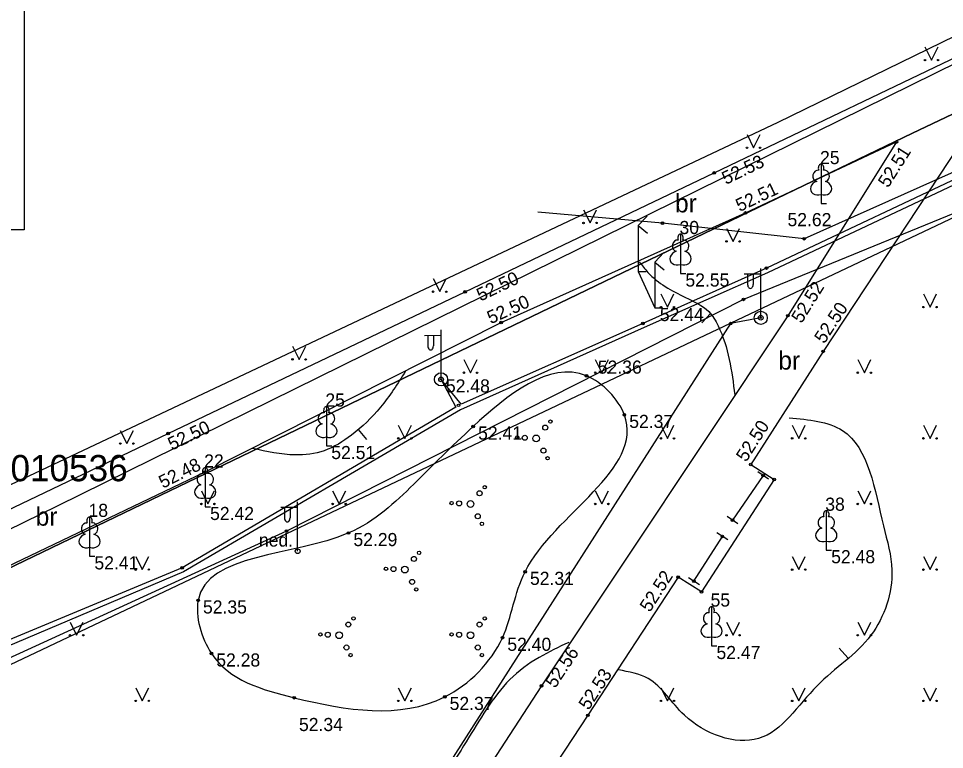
# Model space of a CAD drawing. Extents: x 619806 to 620082, y 405176 to 405386.
# Drawn here: x 619897.79 to 619933.05, y 405325.65 to 405353.49 of the extents above; entities that cross this region are included whole.
import ezdxf

# ---------------------------------------------------------------- set-up
doc = ezdxf.new("R2010")
doc.units = 0
for name, color, linetype in [('24', 7, 'Continuous'), ('APGR_SARK_####_####_#', 7, 'Continuous'), ('APGS_ELEM_####_####_#', 7, 'Continuous'), ('APGS_ELEM_####_TKST_#', 7, 'Continuous'), ('APGS_VADP_ZSPR_####_#', 7, 'Continuous'), ('BUVE_SOLS_####_####_#', 7, 'Continuous'), ('CELI_CMAL_####_####_#', 7, 'Continuous'), ('CELI_CSEG_####_TKST_#', 7, 'Continuous'), ('CELI_ELEM_####_####_#', 7, 'Continuous'), ('CELI_REKL_####_####_#', 7, 'Continuous'), ('ELEK_VADP_ZSPR_####_#', 7, 'Continuous'), ('RAMI_PLAN_####_TKST_#', 7, 'Continuous'), ('RAMI_UZMR_####_####_#', 7, 'Continuous'), ('RELJ_AATZ_####_TKST_#', 7, 'Continuous'), ('RELJ_ELEM_####_####_#', 7, 'Continuous'), ('RELJ_HORZ_PAMT_####_#', 7, 'Continuous'), ('ROBZ_PROJ_####_TKST_#', 7, 'Continuous'), ('ROBZ_UZMR_####_####_#', 7, 'Continuous'), ('SAKT_VADP_KABE_####_#', 7, 'Continuous'), ('TERT_DIAM_####_TKST_#', 7, 'Continuous'), ('TERT_ELEM_####_####_#', 7, 'Continuous'), ('TERT_KONT_####_####_#', 7, 'Continuous')]:
    doc.layers.add(name, color=color, linetype=linetype)

msp = doc.modelspace()

# ---------------------------------------------------------------- linework, layer by layer
at = {"layer": '24'}
for p, q in [((619934.749, 405350.522), (619931.837, 405349.12)), ((619931.837, 405349.12), (619818.193, 405294.391))]:
    msp.add_line(p, q, dxfattribs=at)
at = {"layer": 'APGR_SARK_####_####_#'}
msp.add_lwpolyline([(619818.56, 405291.467), (619964.609, 405360.731), (619976.198, 405343.424)], dxfattribs=at)
at = {"layer": 'APGS_ELEM_####_####_#'}
for p, q in [((619926.053, 405342.093), (619926.053, 405343.976)), ((619926.053, 405343.76), (619925.418, 405343.755)), ((619925.553, 405343.756), (619925.553, 405343.364)), ((619925.763, 405343.758), (619925.763, 405343.364)), ((619913.878, 405341.415), (619913.243, 405341.41)), ((619913.378, 405341.411), (619913.378, 405341.019)), ((619913.588, 405341.413), (619913.588, 405341.019)), ((619913.878, 405339.748), (619913.878, 405341.631)), ((619908.418, 405333.2), (619908.418, 405335.083)), ((619908.418, 405334.867), (619907.783, 405334.862)), ((619907.918, 405334.863), (619907.918, 405334.471)), ((619908.128, 405334.865), (619908.128, 405334.471))]:
    msp.add_line(p, q, dxfattribs=at)
for centre, radius in [((619926.053, 405342.093), 0.25), ((619926.053, 405342.093), 0.09), ((619926.053, 405342.093), 0.0225), ((619913.878, 405339.748), 0.25), ((619913.878, 405339.748), 0.09), ((619913.878, 405339.748), 0.0225), ((619908.418, 405333.2), 0.09)]:
    msp.add_circle(centre, radius, dxfattribs=at)
for centre in [(619925.658, 405343.364), (619913.483, 405341.019), (619908.023, 405334.471)]:
    msp.add_ellipse(centre, major_axis=(0, 0.151), ratio=0.695971, start_param=1.570796, end_param=4.712389, dxfattribs=at)
at = {"layer": 'APGS_VADP_ZSPR_####_#'}
for points in [[(619961.504, 405361.726), (619961.549, 405360.889), (619955.561, 405357.47), (619948.629, 405353.911), (619942.586, 405351.309), (619934.737, 405347.784), (619926.308, 405343.807), (619921.62, 405341.722), (619914.616, 405338.589), (619904.064, 405332.419), (619892.947, 405327.707), (619882.253, 405322.432), (619872.343, 405318.394), (619866.043, 405315.914), (619858.147, 405313.031), (619849.141, 405308.474), (619837.591, 405302.476), (619829.867, 405298.738), (619827.533, 405297.619), (619826.332, 405294.789), (619825.868, 405290.973), (619826.009, 405290.873), (619827.279, 405290.766)], [(619961.504, 405361.726), (619961.582, 405360.944), (619961.547, 405359.255), (619942.312, 405349.715), (619925.4, 405342.794), (619907.997, 405333.971), (619887.51, 405324.581), (619867.415, 405316.417), (619859.827, 405308.06), (619845.28, 405301.51), (619837.164, 405301.798), (619827.1, 405298.963), (619826.475, 405294.709), (619826.025, 405290.988), (619827.279, 405290.766)], [(619961.504, 405361.726), (619961.513, 405360.941), (619956.997, 405358.363), (619948.588, 405354.007), (619942.536, 405351.427), (619934.667, 405347.943), (619926.276, 405343.988), (619921.568, 405341.876), (619914.639, 405338.805), (619913.878, 405339.748), (619914.447, 405338.686), (619904.019, 405332.565), (619892.911, 405327.951)], [(619926.053, 405342.093), (619924.906, 405341.871), (619913.437, 405323.942), (619914.167, 405323.421), (619913.311, 405323.727), (619901.199, 405304.503), (619901.88, 405304.137), (619901.118, 405304.337), (619891.212, 405294.458), (619889.151, 405287.633)]]:
    msp.add_lwpolyline(points, dxfattribs=at)
at = {"layer": 'BUVE_SOLS_####_####_#'}
for p, q in [((619926.149, 405336.083), (619924.978, 405334.383)), ((619926.355, 405335.941), (619925.943, 405336.225)), ((619925.184, 405334.241), (619924.772, 405334.525)), ((619923.51, 405332.059), (619924.591, 405333.767)), ((619924.802, 405333.633), (619924.38, 405333.901)), ((619923.721, 405331.925), (619923.299, 405332.193))]:
    msp.add_line(p, q, dxfattribs=at)
at = {"layer": 'CELI_CMAL_####_####_#'}
for points in [[(619991.854, 405321.355), (619987.265, 405327.894), (619980.195, 405338.024), (619973.089, 405348.264), (619967.033, 405357.029), (619962.383, 405363.658), (619953.25, 405359.322), (619947.967, 405356.794), (619934.832, 405350.507), (619928.431, 405340.813), (619925.67, 405336.505), (619926.565, 405335.935), (619923.8, 405331.651)], [(619825.042, 405301.626), (619825.997, 405300.736), (619826.865, 405300.888), (619837.411, 405305.982), (619845.924, 405310.094), (619856.691, 405315.252), (619868.203, 405320.761), (619880.848, 405326.828), (619891.162, 405331.79), (619903.487, 405337.685), (619914.792, 405343.079), (619924.282, 405347.611), (619934.782, 405352.643), (619943.391, 405356.735), (619942.998, 405357.499)], [(619889.516, 405328.858), (619904.867, 405336.211), (619916.17, 405341.916), (619925.47, 405346.087), (619931.221, 405348.79)], [(619931.221, 405348.79), (619927.084, 405342.173), (619917.705, 405328.076), (619912.167, 405319.566), (619908.262, 405313.163), (619901.141, 405301.297), (619895.285, 405291.495)], [(619923.8, 405331.651), (619922.909, 405332.209), (619919.472, 405326.95), (619913.839, 405318.4), (619910.247, 405312.462), (619903.419, 405300.947), (619897.856, 405291.596), (619907.48, 405291.973), (619918.115, 405292.304), (619928.883, 405292.628), (619940.313, 405293.006), (619951.468, 405293.381)]]:
    msp.add_lwpolyline(points, dxfattribs=at)
at = {"layer": 'CELI_ELEM_####_####_#'}
for points in [[(619921.728, 405345.969), (619921.386, 405345.613), (619921.742, 405345.314)], [(619921.386, 405345.613), (619921.386, 405343.861), (619921.685, 405343.861)], [(619922.367, 405344.574), (619922.025, 405344.218), (619922.381, 405343.919)], [(619922.025, 405344.218), (619922.025, 405342.466), (619922.324, 405342.466)]]:
    msp.add_lwpolyline(points, dxfattribs=at)
at = {"layer": 'CELI_REKL_####_####_#'}
msp.add_lwpolyline([(619921.386, 405343.861), (619922.025, 405342.466)], dxfattribs=at)
at = {"layer": 'ELEK_VADP_ZSPR_####_#'}
msp.add_lwpolyline([(619971.958, 405366.357), (619953.365, 405356.579), (619942.947, 405351.901), (619927.707, 405345.105), (619922.312, 405345.694), (619917.565, 405346.118)], dxfattribs=at)
at = {"layer": 'RAMI_PLAN_####_TKST_#'}
msp.add_lwpolyline([(619883.741, 405345.448), (619883.741, 405364.759), (619898.001, 405364.759), (619898.001, 405345.448)], close=True, dxfattribs=at)
at = {"layer": 'RAMI_UZMR_####_####_#'}
msp.add_lwpolyline([(619874.687, 405324.979), (619926.719, 405349.544), (619966.669, 405369.042), (620021.738, 405292.03), (620049.703, 405275.476), (620026.189, 405242.287), (620012.147, 405222.917), (619996.603, 405200.928), (619989.997, 405199.173), (619982.328, 405199.155), (619922.669, 405233.014), (619882.137, 405255.756), (619859.084, 405268.056), (619820.646, 405290.715), (619813.744, 405295.206), (619820.645, 405298.752)], close=True, dxfattribs=at)
at = {"layer": 'RELJ_ELEM_####_####_#'}
for centre in [(619931.221, 405348.79), (619924.282, 405347.611), (619925.47, 405346.087), (619922.312, 405345.694), (619927.707, 405345.105), (619926.276, 405343.988), (619914.792, 405343.079), (619925.4, 405342.794), (619927.084, 405342.173), (619916.17, 405341.916), (619921.568, 405341.876), (619924.906, 405341.871), (619928.431, 405340.813), (619919.417, 405339.883), (619914.544, 405338.758), (619920.859, 405338.396), (619915.104, 405337.953), (619903.487, 405337.685), (619925.67, 405336.505), (619904.867, 405336.211), (619926.149, 405336.083), (619926.565, 405335.935), (619924.978, 405334.383), (619907.997, 405333.971), (619910.356, 405333.895), (619924.591, 405333.767), (619904.019, 405332.565), (619917.079, 405332.417), (619922.909, 405332.209), (619923.51, 405332.059), (619923.8, 405331.651), (619904.626, 405331.328), (619916.216, 405329.906), (619905.132, 405329.307), (619917.705, 405328.076), (619908.283, 405327.62), (619914.02, 405327.653), (619919.472, 405326.95)]:
    msp.add_circle(centre, 0.05, dxfattribs=at)
at = {"layer": 'RELJ_HORZ_PAMT_####_#'}
for p, q in [((619923.816, 405341.896), (619924.155, 405342.264)), ((619911.056, 405337.455), (619910.741, 405337.843)), ((619929.037, 405329.505), (619929.376, 405329.137))]:
    msp.add_line(p, q, dxfattribs=at)
for points in [[(619921.426, 405344.224), (619921.758, 405343.821), (619923.187, 405342.867), (619924.073, 405342.329), (619924.429, 405341.789), (619925.066, 405339.155)], [(619912.527, 405340.062), (619911.571, 405338.683), (619910.462, 405337.62), (619909.43, 405337.031), (619908.327, 405336.869), (619906.693, 405337.117)], [(619927.135, 405338.286), (619929.164, 405337.801), (619930.728, 405334.167), (619931.051, 405332.479), (619930.25, 405330), (619928.199, 405328.075), (619925.971, 405326.066), (619923.148, 405326.954), (619921.766, 405328.348), (619920.633, 405328.681)], [(619918.742, 405329.729), (619917.612, 405329.154), (619916.499, 405328.312), (619915.614, 405327.187), (619914.833, 405325.938), (619914.442, 405325.317), (619914.031, 405324.725), (619913.331, 405323.789), (619912.64, 405322.847), (619911.31, 405320.969), (619910.015, 405319.069), (619908.767, 405317.139), (619908.164, 405316.159), (619907.577, 405315.169), (619906.955, 405314.022), (619906.379, 405312.85), (619905.821, 405311.67), (619905.539, 405311.083), (619905.25, 405310.5), (619905.107, 405310.256), (619904.948, 405310.016), (619904.743, 405309.66), (619904.718, 405309.601), (619904.698, 405309.542), (619904.72, 405309.402), (619904.84, 405309.271), (619905.01, 405309.174), (619905.183, 405309.136), (619905.828, 405309.136)]]:
    msp.add_spline(points, degree=3, dxfattribs=at)
at = {"layer": 'ROBZ_UZMR_####_####_#'}
for p, q in [((619931.837, 405349.12), (619934.749, 405350.522)), ((619818.193, 405294.391), (619931.837, 405349.12))]:
    msp.add_line(p, q, dxfattribs=at)
at = {"layer": 'SAKT_VADP_KABE_####_#'}
msp.add_lwpolyline([(619816.151, 405294.73), (619838.42, 405305.23), (619866.149, 405318.697), (619899.278, 405334.929), (619937.202, 405353.635), (619962.924, 405366.289), (619964.424, 405369.208)], dxfattribs=at)
at = {"layer": 'TERT_ELEM_####_####_#'}
for p, q in [((619932.308, 405352.41), (619932.558, 405351.91)), ((619932.558, 405351.91), (619932.808, 405352.41)), ((619925.531, 405349.07), (619925.781, 405348.57)), ((619925.781, 405348.57), (619926.031, 405349.07)), ((619928.352, 405346.793), (619928.352, 405346.446)), ((619928.352, 405346.446), (619928.552, 405346.446)), ((619919.304, 405346.206), (619919.554, 405345.706)), ((619919.554, 405345.706), (619919.804, 405346.206)), ((619924.75, 405345.5), (619925, 405345)), ((619925, 405345), (619925.25, 405345.5)), ((619922.999, 405344.129), (619922.999, 405343.782)), ((619913.577, 405343.588), (619913.827, 405343.088)), ((619913.827, 405343.088), (619914.077, 405343.588)), ((619922.999, 405343.782), (619923.199, 405343.782)), ((619922.25, 405343), (619922.5, 405342.5)), ((619922.5, 405342.5), (619922.75, 405343)), ((619932.25, 405343), (619932.5, 405342.5)), ((619932.5, 405342.5), (619932.75, 405343)), ((619908.223, 405341.008), (619908.473, 405340.508)), ((619908.473, 405340.508), (619908.723, 405341.008)), ((619914.75, 405340.5), (619915, 405340)), ((619915, 405340), (619915.25, 405340.5)), ((619919.75, 405340.5), (619920, 405340)), ((619920, 405340), (619920.25, 405340.5)), ((619929.75, 405340.5), (619930, 405340)), ((619930, 405340), (619930.25, 405340.5)), ((619912.25, 405338), (619912.5, 405337.5)), ((619912.5, 405337.5), (619912.75, 405338)), ((619922.25, 405338), (619922.5, 405337.5)), ((619922.5, 405337.5), (619922.75, 405338)), ((619927.25, 405338), (619927.5, 405337.5)), ((619927.5, 405337.5), (619927.75, 405338)), ((619932.25, 405338), (619932.5, 405337.5)), ((619932.5, 405337.5), (619932.75, 405338)), ((619901.664, 405337.802), (619901.914, 405337.302)), ((619901.914, 405337.302), (619902.164, 405337.802)), ((619909.513, 405337.557), (619909.513, 405337.21)), ((619909.513, 405337.21), (619909.713, 405337.21)), ((619904.75, 405335.5), (619905, 405335)), ((619905, 405335), (619905.25, 405335.5)), ((619909.75, 405335.5), (619910, 405335)), ((619910, 405335), (619910.25, 405335.5)), ((619919.75, 405335.5), (619920, 405335)), ((619920, 405335), (619920.25, 405335.5)), ((619929.75, 405335.5), (619930, 405335)), ((619930, 405335), (619930.25, 405335.5)), ((619904.897, 405335.236), (619904.897, 405334.889)), ((619904.897, 405334.889), (619905.097, 405334.889)), ((619900.492, 405333.355), (619900.492, 405333.008)), ((619928.55, 405333.589), (619928.55, 405333.242)), ((619900.492, 405333.008), (619900.692, 405333.008)), ((619902.25, 405333), (619902.5, 405332.5)), ((619902.5, 405332.5), (619902.75, 405333)), ((619927.25, 405333), (619927.5, 405332.5)), ((619927.5, 405332.5), (619927.75, 405333)), ((619928.55, 405333.242), (619928.75, 405333.242)), ((619932.25, 405333), (619932.5, 405332.5)), ((619932.5, 405332.5), (619932.75, 405333)), ((619899.75, 405330.5), (619900, 405330)), ((619900, 405330), (619900.25, 405330.5)), ((619924.75, 405330.5), (619925, 405330)), ((619925, 405330), (619925.25, 405330.5)), ((619929.75, 405330.5), (619930, 405330)), ((619930, 405330), (619930.25, 405330.5)), ((619924.182, 405329.94), (619924.182, 405329.593)), ((619924.182, 405329.593), (619924.382, 405329.593)), ((619902.25, 405328), (619902.5, 405327.5)), ((619902.5, 405327.5), (619902.75, 405328)), ((619912.25, 405328), (619912.5, 405327.5)), ((619912.5, 405327.5), (619912.75, 405328)), ((619922.25, 405328), (619922.5, 405327.5)), ((619922.5, 405327.5), (619922.75, 405328)), ((619927.25, 405328), (619927.5, 405327.5)), ((619927.5, 405327.5), (619927.75, 405328)), ((619932.25, 405328), (619932.5, 405327.5)), ((619932.5, 405327.5), (619932.75, 405328))]:
    msp.add_line(p, q, dxfattribs=at)
for points in [[(619928.352, 405347.946), (619928.352, 405346.793)], [(619928.442, 405347.714), (619928.441, 405347.715)], [(619922.999, 405345.282), (619922.999, 405344.129)], [(619923.089, 405345.05), (619923.088, 405345.051)], [(619909.513, 405338.71), (619909.513, 405337.557)], [(619909.603, 405338.478), (619909.602, 405338.479)], [(619904.897, 405336.389), (619904.897, 405335.236)], [(619904.987, 405336.157), (619904.986, 405336.158)], [(619928.55, 405334.742), (619928.55, 405333.589)], [(619900.492, 405334.508), (619900.492, 405333.355)], [(619928.64, 405334.51), (619928.639, 405334.511)], [(619900.582, 405334.276), (619900.581, 405334.277)], [(619924.182, 405331.093), (619924.182, 405329.94)], [(619924.272, 405330.861), (619924.271, 405330.862)]]:
    msp.add_lwpolyline(points, dxfattribs=at)
for centre, radius in [((619932.308, 405351.91), 0.028), ((619932.808, 405351.91), 0.0263), ((619925.531, 405348.569), 0.028), ((619926.031, 405348.569), 0.0263), ((619919.304, 405345.706), 0.028), ((619919.804, 405345.706), 0.0263), ((619924.75, 405345), 0.028), ((619925.25, 405345), 0.0263), ((619913.577, 405343.087), 0.028), ((619914.077, 405343.087), 0.0263), ((619922.25, 405342.5), 0.028), ((619922.75, 405342.5), 0.0263), ((619932.25, 405342.5), 0.028), ((619932.75, 405342.5), 0.0263), ((619908.222, 405340.508), 0.028), ((619908.722, 405340.508), 0.0263), ((619914.75, 405340), 0.028), ((619915.25, 405340), 0.0263), ((619919.75, 405340), 0.028), ((619920.25, 405340), 0.0263), ((619929.75, 405340), 0.028), ((619930.25, 405340), 0.0263), ((619918.044, 405338.139), 0.064), ((619917.848, 405337.908), 0.096), ((619912.25, 405337.5), 0.028), ((619912.75, 405337.5), 0.0263), ((619916.782, 405337.534), 0.064), ((619917.066, 405337.521), 0.096), ((619917.5, 405337.5), 0.128), ((619922.25, 405337.5), 0.028), ((619922.75, 405337.5), 0.0263), ((619927.25, 405337.5), 0.028), ((619927.75, 405337.5), 0.0263), ((619932.25, 405337.5), 0.028), ((619932.75, 405337.5), 0.0263), ((619901.663, 405337.301), 0.028), ((619902.163, 405337.301), 0.0263), ((619917.776, 405337.033), 0.096), ((619917.934, 405336.744), 0.064), ((619915.348, 405335.408), 0.096), ((619915.544, 405335.639), 0.064), ((619904.75, 405335), 0.028), ((619905.25, 405335), 0.0263), ((619909.75, 405335), 0.028), ((619910.25, 405335), 0.0263), ((619914.282, 405335.034), 0.064), ((619914.566, 405335.021), 0.096), ((619915, 405335), 0.128), ((619919.75, 405335), 0.028), ((619920.25, 405335), 0.0263), ((619929.75, 405335), 0.028), ((619930.25, 405335), 0.0263), ((619915.276, 405334.533), 0.096), ((619915.434, 405334.244), 0.064), ((619912.848, 405332.908), 0.096), ((619913.044, 405333.139), 0.064), ((619911.782, 405332.534), 0.064), ((619912.066, 405332.521), 0.096), ((619912.5, 405332.5), 0.128), ((619902.25, 405332.5), 0.028), ((619902.75, 405332.5), 0.0263), ((619927.25, 405332.5), 0.028), ((619927.75, 405332.5), 0.0263), ((619932.25, 405332.5), 0.028), ((619932.75, 405332.5), 0.0263), ((619912.776, 405332.033), 0.096), ((619912.934, 405331.744), 0.064), ((619910.348, 405330.408), 0.096), ((619910.544, 405330.639), 0.064), ((619915.348, 405330.408), 0.096), ((619915.544, 405330.639), 0.064), ((619909.282, 405330.034), 0.064), ((619909.566, 405330.021), 0.096), ((619910, 405330), 0.128), ((619914.282, 405330.034), 0.064), ((619914.566, 405330.021), 0.096), ((619915, 405330), 0.128), ((619899.75, 405330), 0.028), ((619900.25, 405330), 0.0263), ((619924.75, 405330), 0.028), ((619925.25, 405330), 0.0263), ((619929.75, 405330), 0.028), ((619930.25, 405330), 0.0263), ((619910.276, 405329.533), 0.096), ((619915.276, 405329.533), 0.096), ((619910.434, 405329.244), 0.064), ((619915.434, 405329.244), 0.064), ((619902.25, 405327.5), 0.028), ((619902.75, 405327.5), 0.0263), ((619912.25, 405327.5), 0.028), ((619912.75, 405327.5), 0.0263), ((619922.25, 405327.5), 0.028), ((619922.75, 405327.5), 0.0263), ((619927.25, 405327.5), 0.028), ((619927.75, 405327.5), 0.0263), ((619932.25, 405327.5), 0.028), ((619932.75, 405327.5), 0.0263)]:
    msp.add_circle(centre, radius, dxfattribs=at)
for centre, major_axis, ratio, start_param, end_param in [((619928.224, 405347.501), (-0.039, -0.212), 0.861323, 3.141593, 6.283185), ((619928.352, 405347.796), (0, -0.15), 0.707107, 3.14537, 5.287485), ((619928.352, 405347.796), (0, -0.15), 0.707107, 0.995701, 3.137816), ((619928.48, 405347.501), (0.039, -0.212), 0.861323, 0, 3.141593), ((619928.262, 405347.039), (0.307, 0.095), 0.814445, 1.570796, 4.752015), ((619928.442, 405347.039), (-0.307, 0.095), 0.814445, 1.531171, 4.712389), ((619922.999, 405345.132), (0, -0.15), 0.707107, 3.14537, 5.287485), ((619922.999, 405345.132), (0, -0.15), 0.707107, 0.995701, 3.137816), ((619922.871, 405344.837), (-0.039, -0.212), 0.861323, 3.141593, 6.283185), ((619923.127, 405344.837), (0.039, -0.212), 0.861323, 0, 3.141593), ((619922.909, 405344.375), (0.307, 0.095), 0.814445, 1.570796, 4.752015), ((619923.089, 405344.375), (-0.307, 0.095), 0.814445, 1.531171, 4.712389), ((619909.513, 405338.56), (0, -0.15), 0.707107, 3.14537, 5.287485), ((619909.513, 405338.56), (0, -0.15), 0.707107, 0.995701, 3.137816), ((619909.385, 405338.265), (-0.039, -0.212), 0.861323, 3.141593, 6.283185), ((619909.641, 405338.265), (0.039, -0.212), 0.861323, 0, 3.141593), ((619909.423, 405337.803), (0.307, 0.095), 0.814445, 1.570796, 4.752015), ((619909.603, 405337.803), (-0.307, 0.095), 0.814445, 1.531171, 4.712389), ((619904.769, 405335.944), (-0.039, -0.212), 0.861323, 3.141593, 6.283185), ((619904.897, 405336.239), (0, -0.15), 0.707107, 3.14537, 5.287485), ((619904.897, 405336.239), (0, -0.15), 0.707107, 0.995701, 3.137816), ((619905.025, 405335.944), (0.039, -0.212), 0.861323, 0, 3.141593), ((619904.807, 405335.482), (0.307, 0.095), 0.814445, 1.570796, 4.752015), ((619904.987, 405335.482), (-0.307, 0.095), 0.814445, 1.531171, 4.712389), ((619928.55, 405334.592), (0, -0.15), 0.707107, 3.14537, 5.287485), ((619928.55, 405334.592), (0, -0.15), 0.707107, 0.995701, 3.137816), ((619900.492, 405334.358), (0, -0.15), 0.707107, 3.14537, 5.287485), ((619900.492, 405334.358), (0, -0.15), 0.707107, 0.995701, 3.137816), ((619928.422, 405334.297), (-0.039, -0.212), 0.861323, 3.141593, 6.283185), ((619928.678, 405334.297), (0.039, -0.212), 0.861323, 0, 3.141593), ((619900.364, 405334.063), (-0.039, -0.212), 0.861323, 3.141593, 6.283185), ((619900.62, 405334.063), (0.039, -0.212), 0.861323, 0, 3.141593), ((619928.46, 405333.835), (0.307, 0.095), 0.814445, 1.570796, 4.752015), ((619928.64, 405333.835), (-0.307, 0.095), 0.814445, 1.531171, 4.712389), ((619900.402, 405333.601), (0.307, 0.095), 0.814445, 1.570796, 4.752015), ((619900.582, 405333.601), (-0.307, 0.095), 0.814445, 1.531171, 4.712389), ((619924.054, 405330.648), (-0.039, -0.212), 0.861323, 3.141593, 6.283185), ((619924.182, 405330.943), (0, -0.15), 0.707107, 3.14537, 5.287485), ((619924.182, 405330.943), (0, -0.15), 0.707107, 0.995701, 3.137816), ((619924.31, 405330.648), (0.039, -0.212), 0.861323, 0, 3.141593), ((619924.092, 405330.186), (0.307, 0.095), 0.814445, 1.570796, 4.752015), ((619924.272, 405330.186), (-0.307, 0.095), 0.814445, 1.531171, 4.712389)]:
    msp.add_ellipse(centre, major_axis=major_axis, ratio=ratio, start_param=start_param, end_param=end_param, dxfattribs=at)
at = {"layer": 'TERT_KONT_####_####_#'}
msp.add_spline([(619912.845, 405335.757), (619915.104, 405337.953), (619919.417, 405339.883), (619920.859, 405338.396), (619917.079, 405332.417), (619916.216, 405329.906), (619914.02, 405327.653), (619908.283, 405327.62), (619905.132, 405329.307), (619904.626, 405331.328), (619910.356, 405333.895), (619912.845, 405335.757)], degree=3, dxfattribs=at)

# ---------------------------------------------------------------- texts
at = {"layer": 'APGS_ELEM_####_TKST_#'}
msp.add_text('ned.', height=0.5, dxfattribs=at).set_placement((619906.943, 405333.376))
at = {"layer": 'CELI_CSEG_####_TKST_#'}
for p in [(619922.788, 405346.108), (619926.724, 405340.118), (619898.44, 405334.173)]:
    msp.add_text('br', height=0.7, dxfattribs=at).set_placement(p)
at = {"layer": 'RELJ_AATZ_####_TKST_#'}
for s, rotation, p in [(' 52.51', 57.6698, (619930.806, 405346.858)), (' 52.53', 25.6055, (619924.557, 405347.072)), (' 52.51', 25.1738, (619925.08, 405346.04)), (' 52.50', 25.5271, (619915.214, 405342.628)), (' 52.52', 57.9861, (619927.508, 405341.694)), (' 52.50', 24.156, (619915.602, 405341.769)), (' 52.50', 56.563, (619928.37, 405340.921)), (' 52.50', 25.5074, (619903.458, 405336.95)), (' 52.50', 57.3442, (619925.398, 405336.415)), (' 52.48', 26.7816, (619903.121, 405335.494)), (' 52.52', 57.2715, (619921.728, 405330.693)), (' 52.56', 56.3634, (619918.121, 405327.799)), (' 52.53', 57.0523, (619919.398, 405326.962))]:
    msp.add_text(s, height=0.5, rotation=rotation, dxfattribs=at).set_placement(p)
for s, p in [(' 52.62', (619926.886, 405345.582)), (' 52.55', (619922.999, 405343.282)), (' 52.44', (619922.025, 405341.966)), (' 52.36', (619919.662, 405339.964)), (' 52.48', (619913.878, 405339.248)), (' 52.37', (619920.859, 405337.896)), (' 52.41', (619915.104, 405337.453)), (' 52.51', (619909.513, 405336.71)), (' 52.42', (619904.897, 405334.389)), (' 52.29', (619910.356, 405333.395)), (' 52.48', (619928.55, 405332.742)), (' 52.41', (619900.492, 405332.508)), (' 52.31', (619917.079, 405331.917)), (' 52.35', (619904.626, 405330.828)), (' 52.40', (619916.216, 405329.406)), (' 52.47', (619924.182, 405329.093)), (' 52.28', (619905.132, 405328.807)), (' 52.37', (619914.02, 405327.153)), (' 52.34', (619908.283, 405326.35))]:
    msp.add_text(s, height=0.5, dxfattribs=at).set_placement(p)
at = {"layer": 'ROBZ_PROJ_####_TKST_#'}
msp.add_text('94010010536', height=1, dxfattribs=at).set_placement((619893.763, 405335.866))
at = {"layer": 'TERT_DIAM_####_TKST_#'}
for s, p in [(' 25', (619928.127, 405347.946)), (' 30', (619922.774, 405345.282)), (' 25', (619909.288, 405338.71)), (' 22', (619904.672, 405336.389)), (' 18', (619900.267, 405334.508)), (' 38', (619928.325, 405334.742)), (' 55', (619923.957, 405331.093))]:
    msp.add_text(s, height=0.5, dxfattribs=at).set_placement(p)

doc.saveas('drawing.dxf')
